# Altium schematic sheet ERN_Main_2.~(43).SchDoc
size A; SheetNumber: 2; SheetTotal: 3; SPICEModelCacheYVUKJMZF: <root> / <DocumentId>YVUKJMZF</DocumentId> / <CacheFrame Number="0"> / <Model Name="1n5400" Kind="MDL"> / <Text>*1N5400 MCE / * 50V 3A Si Rectifier pkg:DO-201 1,2 / .MODEL 1N5400 D(IS=2.68E-12 RS=0.00977 N=1.17 TT=1.44E-5 CJO=1.24E-10 / + VJ=0.6 M=0.333 BV=66.6 IBV=1E-5 )</Text> / </Model> / <Model Name="led2" Kind="MDL"> / <Text>*Typ RED,GREEN,YELLOW,AMBER GaAs LED: Vf=2.1V Vr=4V If=40mA trr=3uS / *LED Pinout: 1=A, 2=K / .MODEL LED2 D (IS=93.1P RS=42M N=4.61 BV=4 IBV=10U / + CJO=2.97P VJ=.75 M=.333 TT=4.32U)</Text> / </Model> / </CacheFrame> / </root>
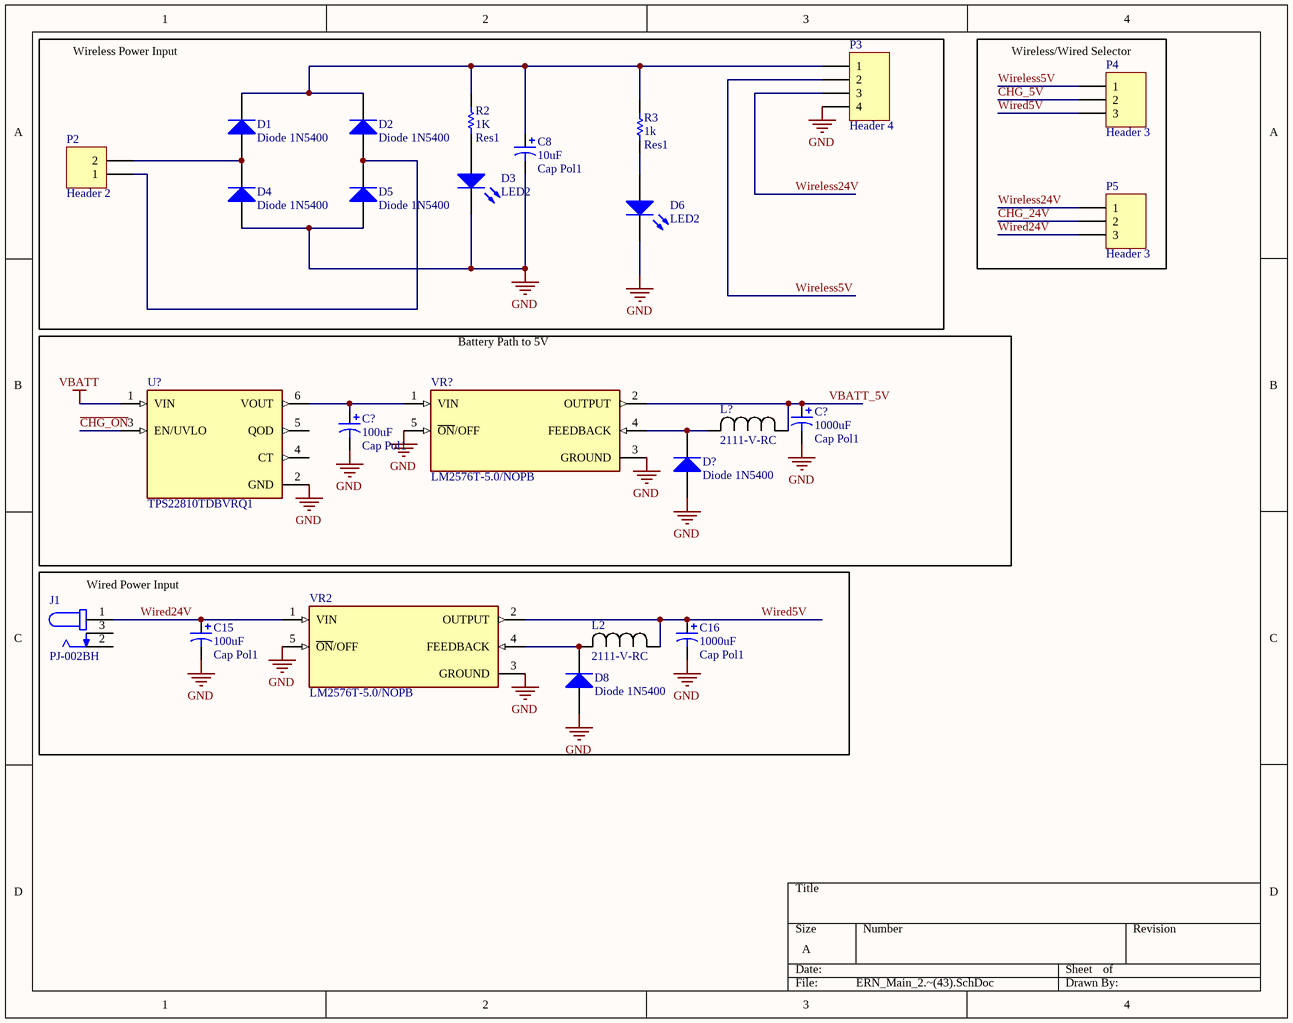
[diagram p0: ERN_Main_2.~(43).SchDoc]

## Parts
(Parts that share a designator on the sheet are numbered #1, #2 ... from top to bottom, then left to right.)
C8  Cap Pol1  value 10uF  [RB7.6-15]
C15  Cap Pol1  value 100uF  [RB7.6-15]
C16  Cap Pol1  value 1000uF  [RB7.6-15]
C?#1  Cap Pol1  value 1000uF  [RB7.6-15]
C?#2  Cap Pol1  value 100uF  [RB7.6-15]
D1  Diode 1N5400  [DO-201AD]
D2  Diode 1N5400  [DO-201AD]
D3  LED2  [3.2X1.6X1.1]
D4  Diode 1N5400  [DO-201AD]
D5  Diode 1N5400  [DO-201AD]
D6  LED2  [3.2X1.6X1.1]
D8  Diode 1N5400  [DO-201AD]
D?  Diode 1N5400  [DO-201AD]
J1  PJ-002BH  [CUI_PJ-002BH]
L2  2111-V-RC  [IND_21XX_27A_V]
L?  2111-V-RC  [IND_21XX_27A_V]
P2  Header 2  [HDR1X2]
P3  Header 4  [HDR1X4]
P4  Header 3  [HDR1X3]
P5  Header 3  [HDR1X3]
R2  Res1  value 1K  [AXIAL-0.3]
R3  Res1  value 1k  [AXIAL-0.3]
U?  TPS22810TDBVRQ1  [SOT95P280X145-6N]
VR2  LM2576T-5.0/NOPB  [TO170P1067X483X1651-5]
VR?  LM2576T-5.0/NOPB  [TO170P1067X483X1651-5]

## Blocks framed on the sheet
Wireless Power Input: C8 D1-D6 P2 P3 R2 R3
Wireless/Wired Selector: P4 P5
Battery Path to 5V: C?#1 C?#2 D? L? U? VR?
Wired Power Input: C15 C16 D8 J1 L2 VR2

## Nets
GND: C8.2 C15.2 C16.2 C?#1.2 C?#2.2 D3.2(K) D4.1(A) D5.1(A) D6.2(K) D8.1(A) D?.1(A) P3.4 U?.2(GND) VR2.3(GROUND) VR2.5(~{ON}/OFF) VR?.3(GROUND) VR?.5(~{ON}/OFF)
VBATT: U?.1(VIN)
~{CHG_ON}: U?.3(EN/UVLO)
CHG_5V: P4.2
CHG_24V: P5.2
VBATT_5V: C?#1.1 L?.1 VR?.2(OUTPUT)
Wired5V: C16.1 L2.1 P4.3 VR2.2(OUTPUT)
Wired24V: C15.1 J1.1 P5.3 VR2.1(VIN)
Wireless5V: P3.2 P4.1
Wireless24V: P3.3 P5.1
NetC8_1: C8.1 D1.2(K) D2.2(K) P3.1 R2.2 R3.2
NetC?#2_1: C?#2.1 U?.6(VOUT) VR?.1(VIN)
NetD1_1: D1.1(A) D4.2(K) P2.2
NetD2_1: D2.1(A) D5.2(K) P2.1
NetD3_1: D3.1(A) R2.1
NetD6_1: D6.1(A) R3.1
NetD8_2: D8.2(K) L2.2 VR2.4(FEEDBACK)
NetD?_2: D?.2(K) L?.2 VR?.4(FEEDBACK)

Not connected (* = marked no-connect by the designer): J1 2 3; U? 4(CT) 5(QOD)

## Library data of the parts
C8 C15 C16 C?#1 C?#2 = Cap Pol1: Polarized Capacitor (Radial)
D1 D2 D4 D5 D8 D? = Diode 1N5400: 3 Amp General Purpose Rectifier
D3 D6 = LED2: Typical RED, GREEN, YELLOW, AMBER GaAs LED
J1 = PJ-002BH: 2.5 x 6.5 mm, 5.0 A, Horizontal, Through Hole, Dc Power Jack Connector; MF: Same Sky
L2 L? = 2111-V-RC: Inductor 68uH; Manufacturer_Name: Bourns Electronics
P2 = Header 2: Header, 2-Pin
P3 = Header 4: Header, 4-Pin
P4 P5 = Header 3: Header, 3-Pin
R2 R3 = Res1: Resistor
U? = TPS22810TDBVRQ1: Automotive 1-channel, 18-V, 2-A, 79-mâ„¦ load switch with adj. rise time and adj. output discharge; MF: Texas Instruments
VR2 VR? = LM2576T-5.0/NOPB: SIMPLE SWITCHERÂ® 40V, 3A Low Component Count Step-Down Regulator; MF: Texas Instruments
